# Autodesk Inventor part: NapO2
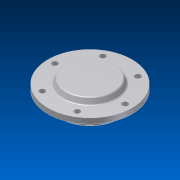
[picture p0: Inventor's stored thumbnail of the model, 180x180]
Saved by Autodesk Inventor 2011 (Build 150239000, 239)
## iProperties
Created: 2011-05
Part Number: NapO2
Document SubType Name: Modeling
Designer: 904Chiaki
Density: 1 g/cm^3
Author: 904Chiaki
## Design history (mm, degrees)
sketch "Sketch1"
  geometry: C1 r 79 at (-7.164, 6.167); 1 further point
  constraints: 1 centre point
  dimensions: "d0" = 158 diameter of C1
extrude "Extrusion1" new body sketch "Sketch1" distance "d1" = 10; taper "d2" = 0 deg
sketch "Sketch2"
  geometry: C1 r 50 at (0, 0); 1 further point
  constraints: 1 centre point
  dimensions: "d4" = 100 diameter of C1
extrude "Extrusion2" join sketch "Sketch2" distance "d5" = 10; taper "d6" = 0 deg
sketch "Sketch3"
  geometry: C1 r 79 at (0, 0) reference; C2 r 50 at (0, 0); 1 further point
  constraints: 1 centre point, 1 coincident
  dimensions: "d7" = 100 diameter of C2
extrude "Extrusion3" cut sketch "Sketch3" distance "d8" = 8; taper "d9" = 0 deg
chamfer "Chamfer1" distance "d10" = 10; stored, may be unused: second distance "d11" = 5, angle "d12" = 45 deg
workplane "Work Plane1"
  workaxis "Work Axis1"
fillet "Fillet1" dims "d17" = 2
fillet "Fillet2" dims "d18" = 2
sketch "Sketch5"
  geometry: C1 r 50 at (0, 0) reference; C2 r 79 at (0, 0) reference; C3 r 54 at (0, 0); 1 further point
  constraints: 1 centre point, 1 coincident
  dimensions: "d19" = 108 diameter of C3
extrude "Extrusion5" join sketch "Sketch5" distance "d20" = 2; taper "d21" = 0 deg
sketch "Sketch6"
  geometry: C1 r 50 at (0, 0) reference; C2 r 54 at (0, 0) reference; C3 r 55 at (0, 0); 1 further point
  constraints: 1 centre point, 1 coincident
  dimensions: "d22" = 110 diameter of C3
extrude "Extrusion6" join sketch "Sketch6" distance "d23" = 18.5; taper "d24" = 0 deg
fillet "Fillet3" dims "d25" = 5
chamfer "Chamfer2" distance "d26" = 1; stored, may be unused: second distance "d27" = 5, angle "d28" = 45 deg
chamfer "Chamfer3" distance "d29" = 1; stored, may be unused: second distance "d30" = 5, angle "d31" = 45 deg
workpoint "Work Point1"
workpoint "Work Point2"
workpoint "Work Point3"
workpoint "Work Point4"
workpoint "Work Point5"
workpoint "Work Point6"
node "Hole2"
body "Solid1"
sketch "Sketch8"
  geometry: 6 further points
hole "Hole1" sketch "Sketch8" diameter "d38" = 11; stored, may be unused: countersink angle "d42" = 90 deg, drill point angle "d44" = 0 deg; dims "d39" = 6, "d40" = 4, "d41" = 2, "d43" = 8
other parameters: "d13" = 90 deg
